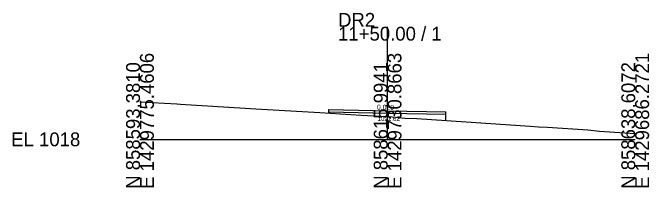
# Model space of a CAD drawing. Extents: x -26 to 103, y -10 to 3026.
# Drawn here: x -25.7 to 102.8, y 2990.3 to 3025.6 of the extents above; entities that cross this region are included whole.
import ezdxf

# ---------------------------------------------------------------- set-up
doc = ezdxf.new("R2010")
doc.units = 0
for name, color, linetype in [('Exist Cross Section Cell', 7, 'Continuous'), ('Exist XS Center Line Elevation Label', 7, 'Continuous'), ('Exist XS Ground Line', 7, 'Continuous'), ('Prop CMT Pvmt Course 1', 7, 'Continuous'), ('Prop CMT Pvmt Surface', 7, 'Continuous'), ('Prop CMT Shld Paved Course 1', 7, 'Continuous'), ('Prop CMT Template Flag', 7, 'Continuous'), ('Prop XS SE Text', 7, 'Continuous')]:
    doc.layers.add(name, color=color, linetype=linetype)

msp = doc.modelspace()

# ---------------------------------------------------------------- linework, layer by layer
at = {"layer": 'Exist Cross Section Cell'}
for p, q in [((50, 3000), (50, 3022.75)), ((0, 3000), (50, 3000)), ((50, 3000), (100, 3000))]:
    msp.add_line(p, q, dxfattribs=at)
at = {"layer": 'Exist XS Ground Line'}
msp.add_lwpolyline([(0, 3007.58), (7.44, 3007.15), (8.19, 3007.1), (23.41, 3006.18), (36.34, 3005.41), (44.64, 3004.9), (48.43, 3004.65), (50, 3004.62), (50.94, 3004.58), (53.56, 3004.28), (55.91, 3004.21), (78.82, 3002.67), (80.48, 3002.5), (82.3, 3002.44), (90.45, 3001.89), (92.79, 3001.68), (100, 3001.16)], dxfattribs=at)
at = {"layer": 'Prop CMT Pvmt Course 1'}
for p, q in [((38.13, 3005.3), (38.13, 3005.46)), ((61.77, 3003.82), (61.77, 3004.99))]:
    msp.add_line(p, q, dxfattribs=at)
at = {"layer": 'Prop CMT Pvmt Surface'}
for p, q in [((38.13, 3006.01), (50, 3005.77)), ((50, 3005.77), (61.77, 3005.53))]:
    msp.add_line(p, q, dxfattribs=at)
at = {"layer": 'Prop CMT Shld Paved Course 1'}
for points in [[(38.13, 3005.46), (38.13, 3006.01)], [(61.77, 3004.99), (61.77, 3005.53)]]:
    msp.add_lwpolyline(points, dxfattribs=at)
at = {"layer": 'Prop CMT Template Flag'}
for p, q in [((50, 3005.23), (38.13, 3005.46)), ((61.77, 3004.99), (50, 3005.23))]:
    msp.add_line(p, q, dxfattribs=at)

# ---------------------------------------------------------------- texts
at = {"layer": 'Exist Cross Section Cell'}
for s, p in [('DR2', (40, 3022.75)), ('11+50.00 / 1', (40, 3019.95)), ('EL 1018', (-26, 2998.6))]:
    msp.add_text(s, height=2.8, dxfattribs=at).set_placement(p)
for s, p in [('E 1429775.4606', (2.8, 2990)), ('E 1429730.8663', (52.8, 2990)), ('E 1429686.2721', (102.8, 2990)), ('N 858593.3810', (0, 2990)), ('N 858615.9941', (50, 2990)), ('N 858638.6072', (100, 2990))]:
    msp.add_text(s, height=2.8, rotation=90, dxfattribs=at).set_placement(p)
at = {"layer": 'Exist XS Center Line Elevation Label'}
msp.add_text('1022.62', height=0.9, dxfattribs=at).set_placement((47.98, 3003.72))
at = {"layer": 'Prop XS SE Text'}
msp.add_text('0.020', height=1, rotation=358.8542, dxfattribs=at).set_placement((47.84, 3006.02))

doc.saveas('drawing.dxf')
